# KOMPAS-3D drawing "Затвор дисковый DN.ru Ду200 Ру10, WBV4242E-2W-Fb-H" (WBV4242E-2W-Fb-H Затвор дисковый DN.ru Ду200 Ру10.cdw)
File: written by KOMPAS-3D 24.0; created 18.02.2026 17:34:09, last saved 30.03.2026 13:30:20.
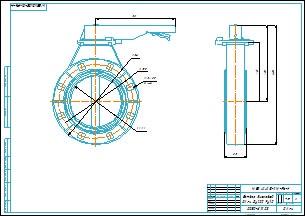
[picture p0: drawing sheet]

Document properties: Автор: R2D2; Форматы листов документа: A2; Полное имя файла: WBV4242E-2W-Fb-H Затвор дисковый DN.ru Ду200 Ру10.m3d; Масса: 7.97; Наименование: Затвор дисковый DN.ru Ду200 Ру10; Количество листов документа: 1; Примечание: D050-81203

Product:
- Component [assembly]: Сборка1  | qty 1  | Масса: 31.771482; Автор: R2D2; source file: исходные материалы\dn200_3d_step.a3d
- Part/product: Затвор дисковый DN.ru Ду200 Ру10  | designation WBV4242E-2W-Fb-H
    Масса: 7.97
    Раздел спецификации: Прочие изделия
    Примечание: D050-81203

Views: Вид 1, Сзади
Referenced files in E:\Работа\Зайцев\WBV4242E-2W-Fb-ISO Затвор дисковый DN.ru Ду50-200 Ру10\DN200\: WBV4242E-2W-Fb-ISO Затвор дисковый DN.ru Ду200 Ру10.m3d
Referenced files in E:\Работа\Зайцев\WBV4242E-2W-Fb-H Затвор дисковый DN.ru Ду50-200 Ру10\DN200\: WBV4242E-2W-Fb-H Затвор дисковый DN.ru Ду200 Ру10.m3d
Referenced files in E:\Работа\Зайцев\Для компаса\: чертеж DN.ru А3.cdt
Referenced files in E:\Работа\Зайцев\WBV4242E-2W-Fb-H Затвор дисковый DN.ru Ду50-200 Ру10\DN200\исходные материалы\: Деталь1 Деталь1.m3d, Деталь2 Деталь2.m3d, dn200_3d_step.a3d
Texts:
  WBV4242E-2W-Fb-H
  чертеж DN.ru А3.cdt
  Затвор дисковый
  DN.ru Ду200 Ру10
  Твердое тело1
  Деталь1
  Деталь1 Деталь1
  Деталь2
  Деталь2 Деталь2
  Сборка1
  Сборка1 Сборка1
  Затвор дисковый DN.ru Ду200 Ру10
  WBV4242E-2W-Fb-H Затвор дисковый DN.ru Ду200 Ру10
Dimensions and other numbers on the sheet: 0; 3; 2; 4; 340; 291,5; 200; 8 отв.; 310; 1:2; 1; 7,97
